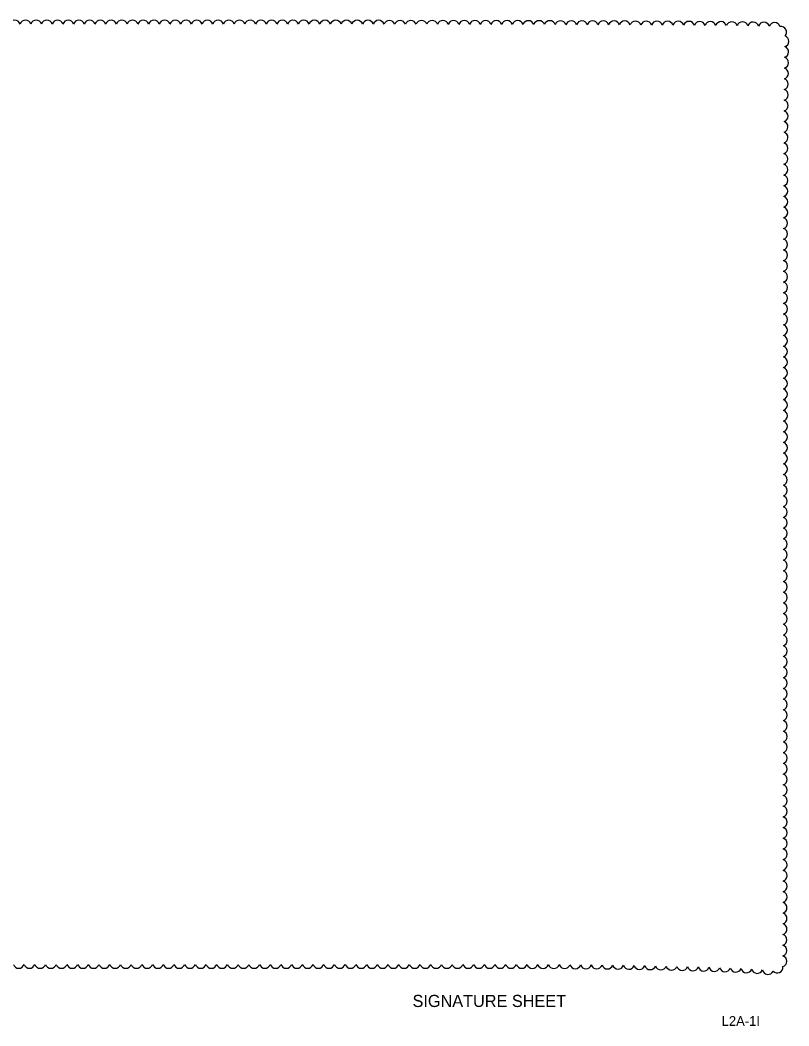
# Model space of a CAD drawing. Extents: x -811 to 10319, y -2309 to 9962.
# Drawn here: x -803.29 to -795.38, y -2309.09 to -2298.74 of the extents above; entities that cross this region are included whole.
import ezdxf

# ---------------------------------------------------------------- set-up
doc = ezdxf.new("R2010")
doc.units = 0
for name, color, linetype in [('PlotBorder_dp', 7, 'Continuous'), ('ScratchEle_dp', 7, 'Continuous'), ('SheetLines_dp', 7, 'Continuous')]:
    doc.layers.add(name, color=color, linetype=linetype)

msp = doc.modelspace()

# ---------------------------------------------------------------- linework, layer by layer
at = {"layer": 'ScratchEle_dp'}
for centre, start, end in [((-803.344, -2298.801), 17.5, 162.5), ((-803.234, -2298.801), 17.5, 162.5), ((-803.124, -2298.801), 17.4999, 162.4999), ((-803.014, -2298.801), 17.4985, 162.4985), ((-802.904, -2298.801), 17.4968, 162.4968), ((-802.794, -2298.801), 17.495, 162.495), ((-802.684, -2298.801), 17.4932, 162.4932), ((-802.574, -2298.801), 17.4913, 162.4913), ((-802.464, -2298.801), 17.4894, 162.4894), ((-802.354, -2298.801), 17.4875, 162.4875), ((-802.243, -2298.801), 17.4855, 162.4855), ((-802.133, -2298.801), 17.4835, 162.4835), ((-802.023, -2298.801), 17.4814, 162.4814), ((-801.913, -2298.801), 17.4792, 162.4792), ((-801.803, -2298.801), 17.477, 162.477), ((-801.693, -2298.802), 17.4748, 162.4748), ((-801.583, -2298.802), 17.4725, 162.4725), ((-801.473, -2298.802), 17.4701, 162.4701), ((-801.363, -2298.802), 17.4676, 162.4676), ((-801.253, -2298.802), 17.4651, 162.4651), ((-801.143, -2298.802), 17.4625, 162.4625), ((-801.033, -2298.802), 17.4599, 162.4599), ((-800.923, -2298.802), 17.4571, 162.4571), ((-800.813, -2298.802), 17.4543, 162.4543), ((-800.703, -2298.802), 17.4514, 162.4514), ((-800.593, -2298.802), 17.4484, 162.4484), ((-800.483, -2298.802), 17.4453, 162.4453), ((-800.373, -2298.802), 17.4421, 162.4421), ((-800.263, -2298.803), 17.4388, 162.4388), ((-800.153, -2298.803), 17.4354, 162.4354), ((-800.043, -2298.803), 17.4318, 162.4318), ((-799.933, -2298.803), 17.4281, 162.4281), ((-799.823, -2298.803), 17.4243, 162.4243), ((-799.712, -2298.803), 17.4204, 162.4204), ((-799.602, -2298.803), 17.4162, 162.4162), ((-799.492, -2298.804), 17.412, 162.412), ((-799.382, -2298.804), 17.4075, 162.4075), ((-799.272, -2298.804), 17.4029, 162.4029), ((-799.162, -2298.804), 17.398, 162.398), ((-799.052, -2298.804), 17.3929, 162.3929), ((-798.942, -2298.805), 17.3876, 162.3876), ((-798.832, -2298.805), 17.3821, 162.3821), ((-798.722, -2298.805), 17.3762, 162.3762), ((-798.612, -2298.805), 17.3701, 162.3701), ((-798.502, -2298.805), 17.3636, 162.3636), ((-798.392, -2298.806), 17.3568, 162.3568), ((-798.282, -2298.806), 17.3496, 162.3496), ((-798.172, -2298.806), 17.342, 162.342), ((-798.062, -2298.807), 17.3339, 162.3339), ((-797.952, -2298.807), 17.3253, 162.3253), ((-797.842, -2298.807), 17.3161, 162.3161), ((-797.732, -2298.808), 17.3062, 162.3062), ((-797.622, -2298.808), 17.2956, 162.2956), ((-797.512, -2298.808), 17.2842, 162.2842), ((-797.402, -2298.809), 17.2719, 162.2719), ((-797.292, -2298.809), 17.2584, 162.2584), ((-797.182, -2298.81), 17.2438, 162.2438), ((-797.072, -2298.81), 17.2277, 162.2277), ((-796.961, -2298.811), 17.2099, 162.2099), ((-796.851, -2298.811), 17.1901, 162.1901), ((-796.741, -2298.812), 17.1679, 162.1679), ((-796.631, -2298.813), 17.1427, 162.1427), ((-796.521, -2298.813), 17.1138, 162.1138), ((-796.411, -2298.814), 17.0803, 162.0803), ((-796.301, -2298.815), 17.0406, 162.0406), ((-796.191, -2298.816), 16.9927, 161.9927), ((-796.081, -2298.817), 16.9334, 161.9334), ((-795.971, -2298.818), 16.857, 161.857), ((-795.861, -2298.819), 16.7534, 161.7534), ((-795.751, -2298.821), 16.6013, 161.6013), ((-795.641, -2298.823), 16.3442, 161.3442), ((-795.531, -2298.826), 15.7356, 160.7356), ((-795.465, -2298.867), 316.2708, 101.2708), ((-795.442, -2298.961), 286.1724, 71.1724), ((-795.444, -2299.071), 286.5791, 71.5791), ((-795.445, -2299.181), 286.7773, 71.7773), ((-795.447, -2299.292), 286.9008, 71.9008), ((-795.448, -2299.402), 286.9872, 71.9872), ((-795.449, -2299.512), 287.0522, 72.0522), ((-795.449, -2299.622), 287.1032, 72.1032), ((-795.45, -2299.732), 287.1448, 72.1448), ((-795.451, -2299.842), 287.1794, 72.1794), ((-795.451, -2299.952), 287.2089, 72.2089), ((-795.452, -2300.062), 287.2343, 72.2343), ((-795.452, -2300.172), 287.2566, 72.2566), ((-795.453, -2300.282), 287.2764, 72.2764), ((-795.453, -2300.392), 287.294, 72.294), ((-795.454, -2300.502), 287.3099, 72.3099), ((-795.454, -2300.612), 287.3243, 72.3243), ((-795.454, -2300.722), 287.3374, 72.3374), ((-795.455, -2300.832), 287.3494, 72.3494), ((-795.455, -2300.942), 287.3605, 72.3605), ((-795.455, -2301.052), 287.3708, 72.3708), ((-795.455, -2301.162), 287.3803, 72.3803), ((-795.456, -2301.272), 287.3892, 72.3892), ((-795.456, -2301.383), 287.3975, 72.3975), ((-795.456, -2301.493), 287.4053, 72.4053), ((-795.456, -2301.603), 287.4126, 72.4126), ((-795.456, -2301.713), 287.4195, 72.4195), ((-795.456, -2301.823), 287.426, 72.426), ((-795.457, -2301.933), 287.4322, 72.4322), ((-795.457, -2302.043), 287.438, 72.438), ((-795.457, -2302.153), 287.4436, 72.4436), ((-795.457, -2302.263), 287.4489, 72.4489), ((-795.457, -2302.373), 287.4539, 72.4539), ((-795.457, -2302.483), 287.4588, 72.4588), ((-795.457, -2302.593), 287.4634, 72.4634), ((-795.457, -2302.703), 287.4678, 72.4678), ((-795.457, -2302.813), 287.472, 72.472), ((-795.457, -2302.923), 287.476, 72.476), ((-795.457, -2303.033), 287.4799, 72.4799), ((-795.457, -2303.143), 287.4837, 72.4837), ((-795.457, -2303.253), 287.4873, 72.4873), ((-795.457, -2303.363), 287.4907, 72.4907), ((-795.458, -2303.473), 287.4941, 72.4941), ((-795.458, -2303.583), 287.4973, 72.4973), ((-795.458, -2303.693), 287.4996, 72.4996), ((-795.458, -2303.804), 287.4988, 72.4988), ((-795.458, -2303.914), 287.4977, 72.4977), ((-795.458, -2304.024), 287.4966, 72.4966), ((-795.458, -2304.134), 287.4954, 72.4954), ((-795.458, -2304.244), 287.4942, 72.4942), ((-795.458, -2304.354), 287.4929, 72.4929), ((-795.458, -2304.464), 287.4916, 72.4916), ((-795.458, -2304.574), 287.4903, 72.4903), ((-795.458, -2304.684), 287.4888, 72.4888), ((-795.458, -2304.794), 287.4874, 72.4874), ((-795.458, -2304.904), 287.4858, 72.4858), ((-795.458, -2305.014), 287.4842, 72.4842), ((-795.458, -2305.124), 287.4825, 72.4825), ((-795.458, -2305.234), 287.4807, 72.4807), ((-795.458, -2305.344), 287.4788, 72.4788), ((-795.458, -2305.454), 287.4768, 72.4768), ((-795.458, -2305.564), 287.4747, 72.4747), ((-795.458, -2305.674), 287.4725, 72.4725), ((-795.458, -2305.784), 287.4702, 72.4702), ((-795.458, -2305.894), 287.4677, 72.4677), ((-795.458, -2306.004), 287.4651, 72.4651), ((-795.458, -2306.114), 287.4622, 72.4622), ((-795.458, -2306.224), 287.4592, 72.4592), ((-795.458, -2306.335), 287.456, 72.456), ((-795.458, -2306.445), 287.4525, 72.4525), ((-795.459, -2306.555), 287.4487, 72.4487), ((-795.459, -2306.665), 287.4446, 72.4446), ((-795.459, -2306.775), 287.4401, 72.4401), ((-795.459, -2306.885), 287.4351, 72.4351), ((-795.459, -2306.995), 287.4296, 72.4296), ((-795.459, -2307.105), 287.4236, 72.4236), ((-795.459, -2307.215), 287.4167, 72.4167), ((-795.459, -2307.325), 287.409, 72.409), ((-795.46, -2307.435), 287.4001, 72.4001), ((-795.46, -2307.545), 287.3897, 72.3897), ((-795.46, -2307.655), 287.3775, 72.3775), ((-795.46, -2307.765), 287.3627, 72.3627), ((-795.461, -2307.875), 287.3443, 72.3443), ((-795.461, -2307.985), 287.3206, 72.3206), ((-795.461, -2308.095), 287.2884, 72.2884), ((-795.462, -2308.205), 287.2408, 72.2408), ((-795.462, -2308.315), 287.1595, 72.1595), ((-795.463, -2308.425), 286.9603, 71.9603), ((-803.303, -2308.44), 197.5, 342.5), ((-803.193, -2308.44), 197.5, 342.5), ((-803.083, -2308.44), 197.5, 342.5), ((-802.973, -2308.44), 197.5, 342.5), ((-802.863, -2308.44), 197.5, 342.5), ((-802.753, -2308.44), 197.5, 342.5), ((-802.643, -2308.44), 197.5, 342.5), ((-802.533, -2308.44), 197.5, 342.5), ((-802.422, -2308.44), 197.5, 342.5), ((-802.312, -2308.44), 197.5, 342.5), ((-802.202, -2308.44), 197.5, 342.5), ((-802.092, -2308.44), 197.5, 342.5), ((-801.982, -2308.44), 197.5, 342.5), ((-801.872, -2308.44), 197.5, 342.5), ((-801.762, -2308.44), 197.5, 342.5), ((-801.652, -2308.44), 197.5, 342.5), ((-801.542, -2308.44), 197.5, 342.5), ((-801.432, -2308.44), 197.5, 342.5), ((-801.322, -2308.44), 197.5, 342.5), ((-801.212, -2308.44), 197.5, 342.5), ((-801.102, -2308.44), 197.5, 342.5), ((-800.992, -2308.44), 197.5, 342.5), ((-800.882, -2308.44), 197.5, 342.5), ((-800.772, -2308.44), 197.5, 342.5), ((-800.662, -2308.44), 197.5, 342.5), ((-800.552, -2308.44), 197.5, 342.5), ((-800.442, -2308.44), 197.5, 342.5), ((-800.332, -2308.44), 197.5, 342.5), ((-800.222, -2308.44), 197.5, 342.5), ((-800.112, -2308.44), 197.5, 342.5), ((-800.002, -2308.44), 197.5, 342.5), ((-799.891, -2308.44), 197.5, 342.5), ((-799.781, -2308.44), 197.5, 342.5), ((-799.671, -2308.44), 197.5, 342.5), ((-799.561, -2308.44), 197.5, 342.5), ((-799.451, -2308.44), 197.5, 342.5), ((-799.341, -2308.44), 197.5, 342.5), ((-799.231, -2308.44), 197.5, 342.5), ((-799.121, -2308.44), 197.5, 342.5), ((-799.011, -2308.44), 197.5, 342.5), ((-798.901, -2308.44), 197.5, 342.5), ((-798.791, -2308.44), 197.5, 342.5), ((-798.681, -2308.44), 197.5, 342.5), ((-798.571, -2308.44), 197.4875, 342.4875), ((-798.461, -2308.44), 197.4461, 342.4461), ((-798.351, -2308.44), 197.4016, 342.4016), ((-798.241, -2308.44), 197.3547, 342.3547), ((-798.131, -2308.44), 197.3053, 342.3053), ((-798.021, -2308.441), 197.2532, 342.2532), ((-797.911, -2308.441), 197.198, 342.198), ((-797.801, -2308.442), 197.1394, 342.1394), ((-797.69, -2308.443), 197.0771, 342.0771), ((-797.58, -2308.444), 197.0107, 342.0107), ((-797.47, -2308.445), 196.9397, 341.9397), ((-797.36, -2308.446), 196.8636, 341.8636), ((-797.25, -2308.447), 196.7816, 341.7816), ((-797.14, -2308.448), 196.6931, 341.6931), ((-797.03, -2308.45), 196.597, 341.597), ((-796.92, -2308.452), 196.4924, 341.4924), ((-796.81, -2308.454), 196.3777, 341.3777), ((-796.7, -2308.456), 196.2513, 341.2513), ((-796.59, -2308.459), 196.111, 341.111), ((-796.48, -2308.462), 195.9541, 340.9541), ((-796.37, -2308.465), 195.8088, 340.8088), ((-796.26, -2308.468), 195.6685, 340.6685), ((-796.15, -2308.472), 195.4928, 340.4928), ((-796.04, -2308.476), 195.2636, 340.2636), ((-795.93, -2308.48), 194.9466, 339.9466), ((-795.82, -2308.486), 194.4656, 339.4656), ((-795.709, -2308.492), 193.5975, 338.5975), ((-795.599, -2308.503), 190.9865, 335.9865), ((-795.504, -2308.487), 222.0186, 7.0186)]:
    msp.add_arc(centre, 0.0577, start, end, dxfattribs=at)

# ---------------------------------------------------------------- texts
at = {"layer": 'PlotBorder_dp'}
msp.add_text('       SIGNATURE SHEET         ', height=0.125, dxfattribs=at).set_placement((-799.579, -2308.896))
at = {"layer": 'SheetLines_dp'}
msp.add_text('L2A-1I', height=0.1, dxfattribs=at).set_placement((-796.075, -2309.09))

doc.saveas('drawing.dxf')
